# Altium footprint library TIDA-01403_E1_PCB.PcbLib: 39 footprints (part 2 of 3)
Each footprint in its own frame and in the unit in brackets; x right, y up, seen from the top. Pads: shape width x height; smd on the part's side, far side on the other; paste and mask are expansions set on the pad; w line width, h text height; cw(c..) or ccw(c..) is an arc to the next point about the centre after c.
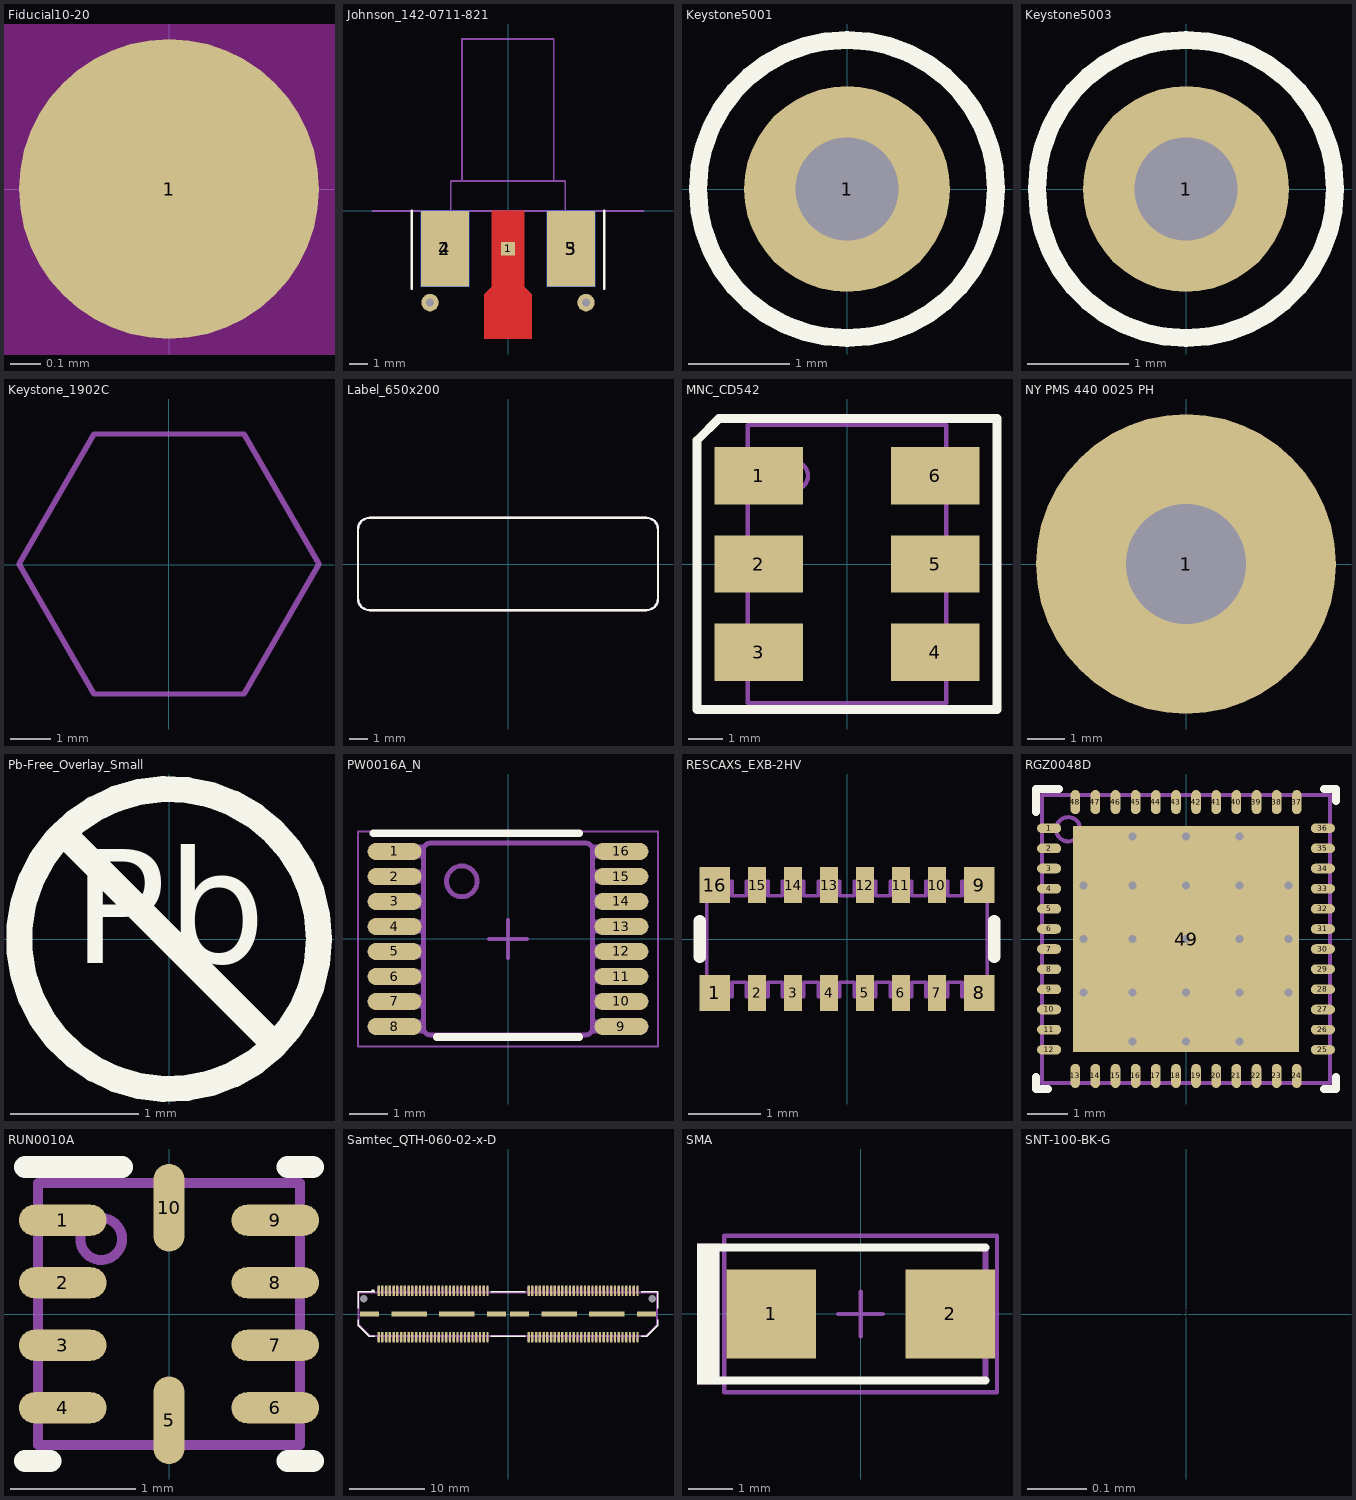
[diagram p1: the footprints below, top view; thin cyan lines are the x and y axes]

## Fiducial10-20 [mm]
pads (1):
  round 1 smd mask+0.5: 1(0,0)
Top Layer keep-out:
  circle w1.178: c0,0 r0.5

## Johnson_142-0711-821 [mil] "SMA JACK EDGE MNT, SMT"
height 140
pads (7):
  rect 30x30 smd: 1(0,-82.5)
  rect 105x165 smd: 2(-137.5,-82.5) 3(137.5,-82.5)
  rect 105x165 smd far side: 4(-137.5,-82.5) 5(137.5,-82.5)
  round 38 hole 18: ""(-170,-200) ""(170,-200)
Top Layer:
  region: -51.5,-279.35 -51.5,-181.5 -35,-165 -35,0 35,0 35,-165 51.5,-181.5 51.5,-279.35
Top Overlay:
  lines w6: -210,-170 -210,0 ; 210,-170 210,0
Mechanical 1:
  lines w3.94: -295.28,0 295.28,0
Mechanical 5:
  lines w3.94: -100.01,64.99 -100.01,374.99 99.99,374.99 99.99,64.99 ; -93.01,-0.01 -93.01,-150.01 -125.01,-150.01 -125.01,-0.01 ; -15.01,-0.01 -15.01,-140.01 ; 14.99,-0.01 14.99,-140.01 ; 92.99,-0.01 92.99,-150.01 124.99,-150.01 124.99,-0.01 ; -125.01,-0.01 124.99,-0.01 ; -125.01,-0.01 -125.01,64.99 124.99,64.99 124.99,-0.01 ; -15.01,-140.01 14.99,-140.01 ; -15.01,-140.01 -5.01,-150.01 4.99,-150.01 14.99,-140.01
  text ".Designator" at -39.37,9.84 h25
3D body "142-0711-821.stp": height 140, standoff -110, extent -125,-150.01 124.99,374.99

## Keystone5001 [mil] "For Keystone 500x miniature loop terminals"
height 181.1
pads (1):
  round 80 hole 40: 1(0,0)
Top Overlay:
  circle w7: c0,0 r58
Mechanical 5:
  circle w5: c0,0 r58.31
  text ".Designator" at -45,-10 h30
3D body "Keystone_5001.stp": height 181.97, standoff -118.11, extent -49,-49 49.04,49.24

## Keystone5003 [mil] "For Keystone 500x miniature loop terminals"
height 181.1
pads (1):
  round 80 hole 40: 1(0,0)
Top Overlay:
  circle w7: c0,0 r58
Mechanical 5:
  circle w5: c0,0 r58.31
  text ".Designator" at -45,-10 h30
3D body "Keystone_5003.stp": height 181.97, standoff -118.11, extent -49,-49 49.04,49.24

## Keystone_1902C [mm] "Hex Standoff, 4-40 threaded, nylon"
height 12.7
Mechanical 5:
  lines w0.127: -3.69,0.012 -1.843,-3.188 1.852,-3.188 3.7,0.012 1.852,3.212 -1.843,3.212 -3.69,0.012
  text ".Designator" at -1.524,-0.508 h0.76
3D body "Keystone_1902C.stp": height 12.73, standoff 0.03, extent -3.682,-3.2 3.708,3.2

## Label_650x200 [mm] "Thermal Transfer Label"
height 0.025
Top Overlay:
  lines w0.127: -8.255,-1.905 ccw(c-7.62,-1.905) -7.62,-2.54 7.62,-2.54 ccw(c7.62,-1.905) 8.255,-1.905 8.255,1.905 ccw(c7.62,1.905) 7.62,2.54 -7.62,2.54 ccw(c-7.62,1.905) -8.255,1.905 -8.255,-1.905
Mechanical 5:
  lines w0.127: -8.255,-1.905 ccw(c-7.62,-1.905) -7.62,-2.54 7.62,-2.54 ccw(c7.62,-1.905) 8.255,-1.905 8.255,1.905 ccw(c7.62,1.905) 7.62,2.54 -7.62,2.54 ccw(c-7.62,1.905) -8.255,1.905 -8.255,-1.905
  text ".Designator" at -1.524,-0.508 h0.76
3D body: height 0.03, standoff 0, extent -8.256,-2.541 8.256,2.541

## MNC_CD542 [mil] "Mini-Circuits recommended land pattern 98-CD.doc rev K 11/06/06"
height 112
pads (6):
  rect 100x65 smd: 1(-100,100) 2(-100,0) 3(-100,-100) 4(100,-100) 5(100,0) 6(100,100)
Top Overlay:
  lines w10: -170,-165 -170,0 -170,140 -145,165 0,165 170,165 170,0 170,-165 0,-165 -170,-165
Mechanical 5:
  circle w5: c-60,100 r15.81
  lines w5: -112.5,-115 -141,-115 -141,-85 -112.5,-85 ; -112.5,-15 -141,-15 -141,15 -112.5,15 ; -112.5,85 -141,85 -141,115 -112.5,115 ; 112.5,-115 141,-115 141,-85 112.5,-85 ; 112.5,-15 141,-15 141,15 112.5,15 ; 112.5,85 141,85 141,115 112.5,115 ; -112.5,-157.5 0,-157.5 112.5,-157.5 112.5,0 112.5,157.5 0,157.5 -112.5,157.5 -112.5,0 -112.5,-157.5
  text ".Designator" at -70,-20 h30
3D body: height 10, standoff 0, extent -140.98,-114.98 -112.52,-85.02
3D body: height 10, standoff 0, extent -140.98,-14.98 -112.52,14.98
3D body: height 112, standoff 0, extent -112.48,-157.48 112.48,157.48
3D body: height 10, standoff 0, extent -140.98,85.02 -112.52,114.98
3D body: height 10, standoff 0, extent 112.52,-114.98 140.98,-85.02
3D body: height 10, standoff 0, extent 112.52,-14.98 140.98,14.98
3D body: height 10, standoff 0, extent 112.52,85.02 140.98,114.98
3D body: height 112.01, standoff 110, extent -75.79,84.21 -44.21,115.79

## NY PMS 440 0025 PH [mm] "4-40 nylon screw and mounting hole"
height 1.905
pads (1):
  round 8 hole 3.2: 1(0,0)
Mechanical 5:
  circle w0.127: c0,0 r3.789
  text ".Designator" at -1.524,-0.508 h0.76
3D body "B_F_NY PMS 440 0025 PH.stp": height 2.69, standoff -8.74, extent -3.302,-3.3 3.296,3.3

## Pb-Free_Overlay_Small [mm]
Top Overlay:
  circle w0.203: c0,0 r1.168
  lines w0.203: -0.826,0.826 0.826,-0.826
  text "Pb" at -0.752,-0.48 h1.52

## PW0016A_N [mm] "TSOP, 16-Leads, Body 5x4.4mm, Pitch 0.65mm, IPC Medium Density"
height 1.2
pads (16):
  oval 1.4x0.45 smd: 1(-2.95,2.275) 2(-2.95,1.625) 3(-2.95,0.975) 4(-2.95,0.325) 5(-2.95,-0.325) 6(-2.95,-0.975) 7(-2.95,-1.625) 8(-2.95,-2.275) 9(2.95,-2.275) 10(2.95,-1.625) 11(2.95,-0.975) 12(2.95,-0.325) 13(2.95,0.325) 14(2.95,0.975) 15(2.95,1.625) 16(2.95,2.275)
Top Overlay:
  lines w0.2: -3.5,2.75 1.85,2.75 ; -1.85,-2.55 1.85,-2.55
Mechanical 5:
  drawing of 202 lines, arcs and shapes, not listed
  text ".Designator" at -1.854,-0.508 h0.76
Mechanical 15:
  lines w0.05: -3.9,-2.8 -3.9,2.8 3.9,2.8 3.9,-2.8 -3.9,-2.8
  lines w0.1: -0.5,0 0.5,0 ; 0,-0.5 0,0.5
3D body "PW0016A.stp": height 1, standoff 0, extent -3.21,-2.5 3.21,2.5

## RESCAXS_EXB-2HV [mm] "Panasonic Resistor Array"
height 0.55
pads (16):
  rect 0.425x0.5 smd mask+0.07: 1(-1.837,-0.75) 8(1.837,-0.75) 9(1.837,0.75) 16(-1.837,0.75)
  rect 0.25x0.5 smd mask+0.07: 2(-1.25,-0.75) 3(-0.75,-0.75) 4(-0.25,-0.75) 5(0.25,-0.75) 6(0.75,-0.75) 7(1.25,-0.75) 10(1.25,0.75) 11(0.75,0.75) 12(0.25,0.75) 13(-0.25,0.75) 14(-0.75,0.75) 15(-1.25,0.75)
Top Overlay:
  lines w0.17: -2.05,-0.25 -2.05,0.25 ; 2.05,-0.25 2.05,0.25
Mechanical 5:
  lines w0.05: -1.95,-0.8 -1.6,-0.8 -1.6,-0.6 -1.4,-0.6 -1.4,-0.8 -1.1,-0.8 -1.1,-0.6 -0.9,-0.6 -0.9,-0.8 -0.6,-0.8 -0.6,-0.6 -0.4,-0.6 -0.4,-0.8 -0.1,-0.8 -0.1,-0.6 0.1,-0.6 0.1,-0.8 0.4,-0.8 0.4,-0.6 0.6,-0.6 0.6,-0.8 0.9,-0.8 0.9,-0.6 1.1,-0.6 1.1,-0.8 1.4,-0.8 1.4,-0.6 1.6,-0.6 1.6,-0.8 1.95,-0.8 1.95,0.8 1.6,0.8 1.6,0.6 1.4,0.6 1.4,0.8 1.1,0.8 1.1,0.6 0.9,0.6 0.9,0.8 0.6,0.8 0.6,0.6 0.4,0.6 0.4,0.8 0.1,0.8 0.1,0.6 -0.1,0.6 -0.1,0.8 -0.4,0.8 -0.4,0.6 -0.6,0.6 -0.6,0.8 -0.9,0.8 -0.9,0.6 -1.1,0.6 -1.1,0.8 -1.4,0.8 -1.4,0.6 -1.6,0.6 -1.6,0.8 -1.95,0.8 -1.95,-0.8
  text ".Designator" at -0.9,-0.25 h0.76
3D body: height 0.55, standoff 0.52, extent -1.949,-0.449 1.949,0.449
3D body: height 0.55, standoff 0, extent -1.949,-0.799 1.949,0.799

## RGZ0048D [mm] "QFN, 48-Leads, Body 7x7mm, Pitch 0.5mm, Thermal Pad 5.6x5.6mm, TI Recommended"
height 1
pads (49):
  oval 0.6x0.24 smd: 1(-3.4,2.75) 2(-3.4,2.25) 3(-3.4,1.75) 4(-3.4,1.25) 5(-3.4,0.75) 6(-3.4,0.25) 7(-3.4,-0.25) 8(-3.4,-0.75) 9(-3.4,-1.25) 10(-3.4,-1.75) 11(-3.4,-2.25) 12(-3.4,-2.75) 25(3.4,-2.75) 26(3.4,-2.25) 27(3.4,-1.75) 28(3.4,-1.25) 29(3.4,-0.75) 30(3.4,-0.25) 31(3.4,0.25) 32(3.4,0.75) 33(3.4,1.25) 34(3.4,1.75) 35(3.4,2.25) 36(3.4,2.75)
  oval 0.24x0.6 smd: 13(-2.75,-3.4) 14(-2.25,-3.4) 15(-1.75,-3.4) 16(-1.25,-3.4) 17(-0.75,-3.4) 18(-0.25,-3.4) 19(0.25,-3.4) 20(0.75,-3.4) 21(1.25,-3.4) 22(1.75,-3.4) 23(2.25,-3.4) 24(2.75,-3.4) 37(2.75,3.4) 38(2.25,3.4) 39(1.75,3.4) 40(1.25,3.4) 41(0.75,3.4) 42(0.25,3.4) 43(-0.25,3.4) 44(-0.75,3.4) 45(-1.25,3.4) 46(-1.75,3.4) 47(-2.25,3.4) 48(-2.75,3.4)
  rect 5.6x5.6 smd paste-2.8: 49(0,0)
via 1.334,-2.55 diameter 0.5 hole 0.2
via 0,-2.55 diameter 0.5 hole 0.2
via -1.334,-2.55 diameter 0.5 hole 0.2
via 2.55,-1.334 diameter 0.5 hole 0.2
via 1.334,-1.334 diameter 0.5 hole 0.2
via 0,-1.334 diameter 0.5 hole 0.2
via -1.334,-1.334 diameter 0.5 hole 0.2
via -2.55,-1.334 diameter 0.5 hole 0.2
via 2.55,0 diameter 0.5 hole 0.2
via 1.334,0 diameter 0.5 hole 0.2
via 0,0 diameter 0.5 hole 0.2
via -1.334,0 diameter 0.5 hole 0.2
via -2.55,0 diameter 0.5 hole 0.2
via 2.55,1.334 diameter 0.5 hole 0.2
via 1.334,1.334 diameter 0.5 hole 0.2
via 0,1.334 diameter 0.5 hole 0.2
via -1.334,1.334 diameter 0.5 hole 0.2
via -2.55,1.334 diameter 0.5 hole 0.2
via 1.334,2.55 diameter 0.5 hole 0.2
via 0,2.55 diameter 0.5 hole 0.2
via -1.334,2.55 diameter 0.5 hole 0.2
Top Overlay:
  lines w0.2: -3.725,-3.425 -3.725,-3.725 -3.425,-3.725 ; -3.725,3.15 -3.725,3.725 -3.15,3.725 ; 3.425,-3.725 3.725,-3.725 3.725,-3.425 ; 3.425,3.725 3.725,3.725 3.725,3.425
Top Paste:
  rectangle: 0.1,-1.234 1.234,-0.1
  rectangle: 1.434,-1.234 2.568,-0.1
  region: -1.434,-0.1 -2.568,-0.1 -2.568,-1.234 -1.434,-1.234
  region: -0.1,-0.1 -1.234,-0.1 -1.234,-1.234 -0.1,-1.234
  region: -0.1,-1.434 -1.234,-1.434 -1.234,-2.568 -0.1,-2.568
  region: -1.434,-1.434 -2.568,-1.434 -2.568,-2.568 -1.434,-2.568
  rectangle: 1.434,-2.568 2.568,-1.434
  rectangle: 0.1,-2.568 1.234,-1.434
  rectangle: 0.1,1.434 1.234,2.568
  rectangle: 1.434,1.434 2.568,2.568
  region: -1.434,2.568 -2.568,2.568 -2.568,1.434 -1.434,1.434
  region: -0.1,2.568 -1.234,2.568 -1.234,1.434 -0.1,1.434
  region: -0.1,1.234 -1.234,1.234 -1.234,0.1 -0.1,0.1
  region: -1.434,1.234 -2.568,1.234 -2.568,0.1 -1.434,0.1
  rectangle: 1.434,0.1 2.568,1.234
  rectangle: 0.1,0.1 1.234,1.234
Mechanical 5:
  circle w0.1: c-2.925,2.725 r0.3
  lines w0.1: -3.575,-3.575 3.575,-3.575 3.575,3.575 -3.575,3.575 -3.575,-3.575
  text ".Designator" at -1.854,-0.508 h0.76
3D body: height 1, standoff 0, extent -3.575,-3.575 3.575,3.575
3D body: height 1.01, standoff 0.5, extent -3.224,2.426 -2.626,3.024

## RUN0010A [mm]
height 0.8
pads (10):
  oval 0.7x0.25 smd: 1(-0.85,0.75) 2(-0.85,0.25) 3(-0.85,-0.25) 4(-0.85,-0.75) 6(0.85,-0.75) 7(0.85,-0.25) 8(0.85,0.25) 9(0.85,0.75)
  oval 0.25x0.7 smd: 5(0,-0.85) 10(0,0.85)
Top Overlay:
  lines w0.178: -1.15,-1.175 -0.95,-1.175 ; -1.15,1.175 -0.375,1.175 ; 0.95,-1.175 1.15,-1.175 ; 0.95,1.175 1.15,1.175
Mechanical 5:
  circle w0.08: c-0.543,0.6 r0.168
  lines w0.08: -1.05,-1.05 1.05,-1.05 1.05,1.05 -1.05,1.05 -1.05,-1.05
  text ".Designator" at -0.85,-0.25 h0.76
3D body: height 0.8, standoff 0, extent -1.049,-1.049 1.049,1.049
3D body: height 0.81, standoff 0.5, extent -0.71,0.433 -0.376,0.767

## Samtec_QTH-060-02-x-D [mil] "Header, 19.7mil, 60x2,, SMT"
height 280.1
pads (130):
  rect 12x57 smd: 1(-679.25,122) 2(-679.25,-121.5) 3(-659.55,122) 4(-659.55,-121.5) 5(-639.85,122) 6(-639.85,-121.5) 7(-620.15,122) 8(-620.15,-121.5) 9(-600.45,122) 10(-600.45,-121.5) 11(-580.75,122) 12(-580.75,-121.5) 13(-561.05,122) 14(-561.05,-121.5) 15(-541.35,122) 16(-541.35,-121.5) 17(-521.65,122) 18(-521.65,-121.5) 19(-501.95,122) 20(-501.95,-121.5) 21(-482.25,122) 22(-482.25,-121.5) 23(-462.55,122) 24(-462.55,-121.5) 25(-442.85,122) 26(-442.85,-121.5) 27(-423.15,122) 28(-423.15,-121.5) 29(-403.45,122) 30(-403.45,-121.5) 31(-383.75,122) 32(-383.75,-121.5) 33(-364.05,122) 34(-364.05,-121.5) 35(-344.35,122) 36(-344.35,-121.5) 37(-324.65,122) 38(-324.65,-121.5) 39(-304.95,122) 40(-304.95,-121.5) 41(-285.25,122) 42(-285.25,-121.5) 43(-265.55,122) 44(-265.55,-121.5) 45(-245.85,122) 46(-245.85,-121.5) 47(-226.15,122) 48(-226.15,-121.5) 49(-206.45,122) 50(-206.45,-121.5) 51(-186.75,122) 52(-186.75,-121.5) 53(-167.05,122) 54(-167.05,-121.5) 55(-147.35,122) 56(-147.35,-121.5) 57(-127.65,122) 58(-127.65,-121.5) 59(-107.95,122) 60(-107.95,-121.5) 61(108.25,122) 62(108.25,-121.5) 63(127.95,122) 64(127.95,-121.5) 65(147.65,122) 66(147.65,-121.5) 67(167.35,122) 68(167.35,-121.5) 69(187.05,122) 70(187.05,-121.5) 71(206.75,122) 72(206.75,-121.5) 73(226.45,122) 74(226.45,-121.5) 75(246.15,122) 76(246.15,-121.5) 77(265.85,122) 78(265.85,-121.5) 79(285.55,122) 80(285.55,-121.5) 81(305.25,122) 82(305.25,-121.5) 83(324.95,122) 84(324.95,-121.5) 85(344.65,122) 86(344.65,-121.5) 87(364.35,122) 88(364.35,-121.5) 89(384.05,122) 90(384.05,-121.5) 91(403.75,122) 92(403.75,-121.5) 93(423.45,122) 94(423.45,-121.5) 95(443.15,122) 96(443.15,-121.5) 97(462.85,122) 98(462.85,-121.5) 99(482.55,122) 100(482.55,-121.5) 101(502.25,122) 102(502.25,-121.5) 103(521.95,122) 104(521.95,-121.5) 105(541.65,122) 106(541.65,-121.5) 107(561.35,122) 108(561.35,-121.5) 109(581.05,122) 110(581.05,-121.5) 111(600.75,122) 112(600.75,-121.5) 113(620.45,122) 114(620.45,-121.5) 115(640.15,122) 116(640.15,-121.5) 117(659.85,122) 118(659.85,-121.5) 119(679.55,122) 120(679.55,-121.5)
  round 0 hole 40 unplated: MH1(-757.55,80) MH2(757.85,80)
  rect 100x25 smd: MP1(-726.25,0) MP4(-61.25,0) MP5(61.25,0) MP8(726.25,0)
  rect 185x25 smd: MP2(-518.75,0) MP3(-268.75,0) MP6(268.75,0) MP7(518.75,0)
Top Overlay:
  rectangle: -717.9,117.45 -700,128
  lines w7.87: -787.51,-30 -787.51,-57.55 -727.51,-117.55 -700,-117.55 ; -787.51,30 -787.51,117.45 -700,117.45 ; -90,-117.55 90,-117.55 ; -90,117.45 90,117.45 ; 700,-117.55 727.49,-117.55 787.49,-57.55 787.49,-30 ; 700,117.45 787.49,117.45 787.49,30
Mechanical 5:
  drawing of 378 lines, arcs and shapes, not listed
  text ".Designator" at -5,0 h25
3D body "Samtec-QTH-060-02-F-D-A.stp": height 288.11, standoff -27, extent -787.51,-140.04 787.5,139.96

## SMA [mm] "Molded Diode, 2-Leads, Body 4.3x2.6mm, IPC Medium Density, based on OnSemi component dimensions and land pattern"
height 2.27
pads (2):
  rect 2x2 smd: 1(-2,0) 2(2,0)
Top Overlay:
  rectangle: -3.658,-1.575 -3.15,1.575
  lines w0.178: -3.327,-1.486 2.794,-1.486 ; -3.327,1.486 2.794,1.486
Mechanical 5:
  rectangle: -3.658,-1.575 -3.15,1.575
  lines w0.127: -3.327,-1.486 2.794,-1.486 2.794,1.486 -3.327,1.486
  text ".Designator" at -2.769,-0.33 h0.76
Mechanical 15:
  lines w0.1: -0.5,0 0.5,0 ; 0,-0.5 0,0.5 ; -3.05,-1.75 -3.05,1.75 3.05,1.75 3.05,-1.75 -3.05,-1.75
3D body "SMA_nominal.stp": height 2.42, standoff 0.02, extent -2.6,-1.3 2.6,1.3

## SNT-100-BK-G [mil] "Samtec STEP model"
height 345
pads (1):
  round 1 on Mech3: 0(0,0)
3D body "SNT-100-XX-X.stp": height 344, standoff 104, extent -100,-50.05 100,50.05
